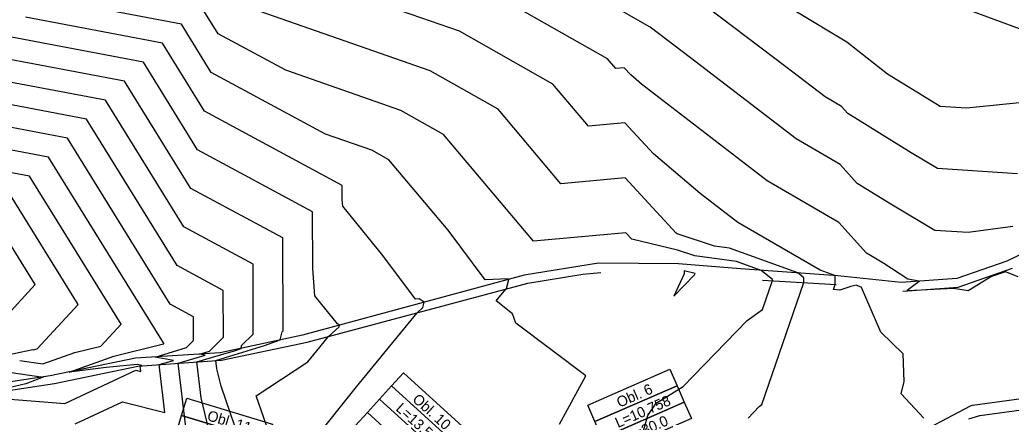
# Model space of a CAD drawing. Extents: x -549394 to -546608, y -1037055 to -1033629.
# Drawn here: x -548286 to -547954.3, y -1035512.1 to -1035379.1 of the extents above; entities that cross this region are included whole.
import ezdxf

# ---------------------------------------------------------------- set-up
doc = ezdxf.new("R2010")
doc.units = 0
for name, color, linetype in [('hlavni_vrst', 7, 'Continuous'), ('hrana_L', 7, 'Continuous'), ('norm_vrst', 7, 'Continuous'), ('x_popis_oblouky_C11', 7, 'Continuous')]:
    doc.layers.add(name, color=color, linetype=linetype)

msp = doc.modelspace()

# ---------------------------------------------------------------- linework, layer by layer
at = {"layer": 'hlavni_vrst'}
for p, q in [((-548148.73, -1035396.14), (-548210.36, -1035374.64)), ((-548009.25, -1035386.63), (-548026.31, -1035376.32)), ((-548251.01, -1035399.66), (-548323.45, -1035385.91)), ((-547995.73, -1035397.25), (-548009.25, -1035386.63)), ((-548125.97, -1035409.06), (-548148.73, -1035396.14)), ((-548228.84, -1035435.52), (-548251.01, -1035399.66)), ((-547980.98, -1035406.38), (-547995.73, -1035397.25)), ((-548104.95, -1035433.96), (-548125.97, -1035409.06)), ((-547978.09, -1035408.12), (-547980.98, -1035406.38)), ((-547969.28, -1035408.7), (-547978.09, -1035408.12)), ((-547948.12, -1035406.53), (-547969.28, -1035408.7)), ((-548282.81, -1035431.42), (-548320.94, -1035424.19)), ((-548252.16, -1035481.01), (-548282.81, -1035431.42)), ((-548083.44, -1035431.99), (-548104.95, -1035433.96)), ((-548066.37, -1035450.47), (-548083.44, -1035431.99)), ((-548198.04, -1035452.13), (-548228.84, -1035435.52)), ((-548197.94, -1035483.23), (-548198.04, -1035452.13)), ((-548066.01, -1035450.77), (-548066.37, -1035450.47)), ((-548053.6, -1035454.84), (-548066.01, -1035450.77)), ((-548048.53, -1035455.53), (-548053.6, -1035454.84)), ((-548025.63, -1035463.85), (-548048.53, -1035455.53)), ((-548023.69, -1035465.43), (-548025.63, -1035463.85)), ((-548023.71, -1035467.04), (-548023.69, -1035465.43)), ((-548037.74, -1035507.93), (-548023.71, -1035467.04)), ((-548258.92, -1035488.34), (-548252.16, -1035481.01)), ((-548198.87, -1035486.25), (-548198.29, -1035483.58)), ((-548198.29, -1035483.58), (-548197.94, -1035483.23)), ((-548267.66, -1035490.52), (-548258.92, -1035488.34)), ((-548218.62, -1035492.6), (-548204.13, -1035488.14)), ((-548204.13, -1035488.14), (-548198.87, -1035486.25)), ((-548278.38, -1035494.31), (-548267.66, -1035490.52)), ((-548286.05, -1035493.2), (-548278.38, -1035494.31)), ((-548220.44, -1035493.13), (-548218.62, -1035492.6)), ((-548220.1, -1035495.92), (-548220.44, -1035493.13)), ((-548218.72, -1035501.7), (-548220.1, -1035495.92)), ((-548212.33, -1035520.2), (-548218.72, -1035501.7)), ((-548042.35, -1035512.4), (-548038.63, -1035508.58)), ((-548038.63, -1035508.58), (-548037.74, -1035507.93))]:
    msp.add_line(p, q, dxfattribs=at)
at = {"layer": 'hrana_L'}
for p, q in [((-547937.9, -1035451.29), (-547955.7, -1035459.9)), ((-548092.43, -1035460.6), (-548117.3, -1035464.61)), ((-548065.59, -1035460.83), (-548092.43, -1035460.6)), ((-548044.85, -1035462.5), (-548065.59, -1035460.83)), ((-548012.33, -1035464.78), (-548044.85, -1035462.5)), ((-547955.7, -1035459.9), (-547972.5, -1035465.74)), ((-547972.01, -1035468.6), (-547953.79, -1035462.21)), ((-548117.3, -1035464.61), (-548191.5, -1035484.65)), ((-548115.99, -1035467.23), (-548097.61, -1035464.2)), ((-548097.61, -1035464.2), (-548091.63, -1035463.63)), ((-547991.14, -1035467), (-548012.33, -1035464.78)), ((-547972.5, -1035465.74), (-547991.14, -1035467)), ((-548189.89, -1035486.99), (-548118.94, -1035468.07)), ((-548118.94, -1035468.07), (-548115.99, -1035467.23)), ((-548037.46, -1035466.21), (-548012.89, -1035467.69)), ((-547990.56, -1035469.94), (-547972.01, -1035468.6)), ((-548191.5, -1035484.65), (-548219, -1035490.61)), ((-548218.54, -1035492.99), (-548189.89, -1035486.99)), ((-548247.31, -1035492.39), (-548275.92, -1035498.32)), ((-548219, -1035490.61), (-548247.31, -1035492.39)), ((-548274.43, -1035500.8), (-548246.59, -1035495.02)), ((-548246.59, -1035495.02), (-548218.54, -1035492.99)), ((-548275.92, -1035498.32), (-548295.3, -1035501.2)), ((-548296.13, -1035504.17), (-548274.43, -1035500.8))]:
    msp.add_line(p, q, dxfattribs=at)
at = {"layer": 'norm_vrst'}
for p, q in [((-548138.95, -1035382.85), (-548199.35, -1035361.78)), ((-547949.34, -1035382.95), (-548005.35, -1035362.14)), ((-548089.36, -1035392.15), (-548129.17, -1035369.56)), ((-548075.07, -1035381.53), (-548096.03, -1035369.52)), ((-548029.66, -1035394.85), (-548062.5, -1035369.98)), ((-548231.93, -1035380.6), (-548264.5, -1035374.42)), ((-548219.67, -1035383.79), (-548225.57, -1035374.25)), ((-548238.29, -1035386.96), (-548284.15, -1035378.25)), ((-548244.65, -1035393.31), (-548303.8, -1035382.08)), ((-548221.97, -1035396.72), (-548231.93, -1035380.6)), ((-548107.67, -1035400.6), (-548138.95, -1035382.85)), ((-548061.55, -1035391.77), (-548075.07, -1035381.53)), ((-548197.06, -1035395.99), (-548219.67, -1035383.79)), ((-548224.26, -1035409.65), (-548238.29, -1035386.96)), ((-548257.37, -1035406.01), (-548335.42, -1035391.2)), ((-548086.62, -1035395.39), (-548089.36, -1035392.15)), ((-548026.29, -1035418.94), (-548061.55, -1035391.77)), ((-548226.55, -1035422.58), (-548244.65, -1035393.31)), ((-548158.51, -1035409.43), (-548197.06, -1035395.99)), ((-548083.81, -1035395.14), (-548086.62, -1035395.39)), ((-548081.59, -1035397.55), (-548083.81, -1035395.14)), ((-548016.58, -1035404.93), (-548029.66, -1035394.85)), ((-548263.73, -1035412.37), (-548331.8, -1035399.45)), ((-548183.76, -1035417.33), (-548221.97, -1035396.72)), ((-548077.98, -1035400.6), (-548081.59, -1035397.55)), ((-548095.78, -1035414.68), (-548107.67, -1035400.6)), ((-548036, -1035432.95), (-548077.98, -1035400.6)), ((-548231.14, -1035448.45), (-548257.37, -1035406.01)), ((-548011.1, -1035408.12), (-548016.58, -1035404.93)), ((-548270.09, -1035418.72), (-548328.18, -1035407.69)), ((-548178.13, -1035434.53), (-548224.26, -1035409.65)), ((-548144.28, -1035417.51), (-548158.51, -1035409.43)), ((-548008.99, -1035410.46), (-548011.1, -1035408.12)), ((-548233.43, -1035461.38), (-548263.73, -1035412.37)), ((-547987.79, -1035423.59), (-548008.99, -1035410.46)), ((-548276.45, -1035425.07), (-548324.56, -1035415.94)), ((-548083.63, -1035413.56), (-548095.78, -1035414.68)), ((-548073.98, -1035424.01), (-548083.63, -1035413.56)), ((-548235.72, -1035474.31), (-548270.09, -1035418.72)), ((-548168.3, -1035422.73), (-548183.76, -1035417.33)), ((-548114.11, -1035453.24), (-548144.28, -1035417.51)), ((-548011.52, -1035427.52), (-548026.29, -1035418.94)), ((-548188.09, -1035443.33), (-548226.55, -1035422.58)), ((-548162.59, -1035425.97), (-548168.3, -1035422.73)), ((-548238.01, -1035487.24), (-548276.45, -1035425.07)), ((-548142.69, -1035449.53), (-548162.59, -1035425.97)), ((-548058.33, -1035437.23), (-548073.98, -1035424.01)), ((-547978.98, -1035428.86), (-547987.79, -1035423.59)), ((-548005.84, -1035433.84), (-548011.52, -1035427.52)), ((-547952.19, -1035430.64), (-547978.98, -1035428.86)), ((-548178.12, -1035439.25), (-548178.13, -1035434.53)), ((-548011.94, -1035446.93), (-548036, -1035432.95)), ((-547994.59, -1035440.8), (-548005.84, -1035433.84)), ((-548266.54, -1035474.38), (-548289.17, -1035437.78)), ((-548177.95, -1035441.52), (-548178.12, -1035439.25)), ((-548045.71, -1035446.96), (-548058.33, -1035437.23)), ((-548164.55, -1035457.95), (-548177.95, -1035441.52)), ((-547979.87, -1035449.61), (-547994.59, -1035440.8)), ((-548280.92, -1035467.75), (-548295.53, -1035444.13)), ((-548188.02, -1035462.34), (-548188.09, -1035443.33)), ((-548208, -1035460.93), (-548231.14, -1035448.45)), ((-548018.22, -1035462.93), (-548045.71, -1035446.96)), ((-548002.69, -1035457.21), (-548011.94, -1035446.93)), ((-547953.77, -1035448.32), (-547968.72, -1035450.35)), ((-548130.34, -1035466.12), (-548142.69, -1035449.53)), ((-548083.25, -1035450.41), (-548114.11, -1035453.24)), ((-548081.26, -1035452.57), (-548083.25, -1035450.41)), ((-548065.91, -1035456.19), (-548081.26, -1035452.57)), ((-547968.72, -1035450.35), (-547979.87, -1035449.61)), ((-548153.64, -1035472.6), (-548164.55, -1035457.95)), ((-548060.11, -1035458.09), (-548065.91, -1035456.19)), ((-548046.17, -1035460), (-548060.11, -1035458.09)), ((-548001.4, -1035458.01), (-548002.69, -1035457.21)), ((-547996.91, -1035460.69), (-548001.4, -1035458.01)), ((-548217.95, -1035469.73), (-548233.43, -1035461.38)), ((-548207.92, -1035484.29), (-548208, -1035460.93)), ((-548187.36, -1035471.47), (-548188.02, -1035462.34)), ((-548037.95, -1035462.98), (-548046.17, -1035460)), ((-547988.82, -1035465.93), (-547996.91, -1035460.69)), ((-548122.65, -1035465.82), (-548130.34, -1035466.12)), ((-548123.14, -1035469.03), (-548122.4, -1035465.99)), ((-548122.4, -1035465.99), (-548122.65, -1035465.82)), ((-548063.68, -1035464.11), (-548067.21, -1035471.66)), ((-548067.21, -1035471.66), (-548060.26, -1035464.43)), ((-548060, -1035464), (-548063.7, -1035463.12)), ((-548063.7, -1035463.12), (-548063.68, -1035464.11)), ((-548060.26, -1035464.43), (-548060, -1035464)), ((-548034.2, -1035466.02), (-548037.95, -1035462.98)), ((-548034.21, -1035466.41), (-548034.2, -1035466.02)), ((-548013.32, -1035464.71), (-548018.22, -1035462.93)), ((-548013.17, -1035464.83), (-548013.32, -1035464.71)), ((-548013.21, -1035467.67), (-548013.17, -1035464.83)), ((-547985.11, -1035466.59), (-547988.82, -1035465.93)), ((-547960.89, -1035465.04), (-547968.71, -1035469.77)), ((-547956.16, -1035463.44), (-547960.89, -1035465.04)), ((-547952, -1035465.1), (-547956.16, -1035463.44)), ((-548290.21, -1035477.82), (-548280.92, -1035467.75)), ((-548126.64, -1035473.22), (-548123.39, -1035469.26)), ((-548123.39, -1035469.26), (-548123.14, -1035469.03)), ((-548037.53, -1035476.08), (-548034.21, -1035466.41)), ((-548013.8, -1035469.41), (-548013.21, -1035467.67)), ((-548007.92, -1035468.32), (-548011.64, -1035469.61)), ((-548006.15, -1035467.95), (-548007.92, -1035468.32)), ((-548004.31, -1035468.7), (-548006.15, -1035467.95)), ((-548004.33, -1035468.76), (-548004.31, -1035468.7)), ((-547997.86, -1035483.64), (-548004.33, -1035468.76)), ((-547989.12, -1035469.6), (-547985.11, -1035466.59)), ((-547973.56, -1035469.05), (-547988.71, -1035469.81)), ((-547968.71, -1035469.77), (-547973.56, -1035469.05)), ((-548217.9, -1035485.35), (-548217.95, -1035469.73)), ((-548179.72, -1035480.84), (-548187.36, -1035471.47)), ((-548152.36, -1035472.55), (-548153.64, -1035472.6)), ((-548150.72, -1035473.64), (-548152.36, -1035472.55)), ((-548011.64, -1035469.61), (-548013.8, -1035469.41)), ((-547988.71, -1035469.81), (-547989.12, -1035469.6)), ((-548280.21, -1035489.2), (-548266.54, -1035474.38)), ((-548227.91, -1035478.53), (-548235.72, -1035474.31)), ((-548153.08, -1035477.17), (-548151.16, -1035475.43)), ((-548151.16, -1035475.43), (-548150.72, -1035473.64)), ((-548121.16, -1035477.49), (-548126.64, -1035473.22)), ((-548227.88, -1035486.42), (-548227.91, -1035478.53)), ((-548173.43, -1035501.96), (-548153.08, -1035477.17)), ((-548120.09, -1035480.68), (-548121.16, -1035477.49)), ((-548042.66, -1035479.8), (-548037.53, -1035476.08)), ((-548182.77, -1035485.09), (-548179.17, -1035481.83)), ((-548179.04, -1035481.28), (-548179.72, -1035480.84)), ((-548179.17, -1035481.83), (-548179.04, -1035481.28)), ((-548096.64, -1035498.3), (-548120.09, -1035480.68)), ((-548064.07, -1035501.86), (-548042.66, -1035479.8)), ((-548222.6, -1035490.02), (-548217.9, -1035485.35)), ((-548211.83, -1035488.17), (-548207.92, -1035484.29)), ((-548186.7, -1035489.89), (-548182.77, -1035485.09)), ((-547990.46, -1035490.94), (-547997.86, -1035483.64)), ((-548280.71, -1035489.32), (-548280.21, -1035489.2)), ((-548254.62, -1035491.72), (-548238.38, -1035487.67)), ((-548240.79, -1035491.98), (-548230.25, -1035488.77)), ((-548238.38, -1035487.67), (-548237.91, -1035487.52)), ((-548237.86, -1035487.32), (-548238.01, -1035487.24)), ((-548237.91, -1035487.52), (-548237.86, -1035487.48)), ((-548237.86, -1035487.48), (-548237.86, -1035487.32)), ((-548230.25, -1035488.77), (-548227.88, -1035486.42)), ((-548213.85, -1035489.75), (-548212.03, -1035489.1)), ((-548212.03, -1035489.1), (-548211.83, -1035488.17)), ((-548292.3, -1035491.67), (-548281.75, -1035489.47)), ((-548281.75, -1035489.47), (-548281.31, -1035489.54)), ((-548281.31, -1035489.54), (-548280.71, -1035489.32)), ((-548269.56, -1035497), (-548254.62, -1035491.72)), ((-548234.6, -1035493.1), (-548240.79, -1035491.98)), ((-548233.1, -1035494.04), (-548223.99, -1035491.41)), ((-548226.77, -1035493.59), (-548218.87, -1035491.3)), ((-548225.97, -1035491.05), (-548222.6, -1035490.02)), ((-548223.99, -1035491.41), (-548225.97, -1035491.05)), ((-548218.87, -1035491.3), (-548213.85, -1035489.75)), ((-548189.65, -1035493.57), (-548186.7, -1035489.89)), ((-547990.11, -1035500.23), (-547990.46, -1035490.94)), ((-548257.17, -1035495.45), (-548269.56, -1035497)), ((-548246.73, -1035494.52), (-548257.17, -1035495.45)), ((-548245.21, -1035494.8), (-548246.73, -1035494.52)), ((-548245.77, -1035494.96), (-548245.21, -1035494.8)), ((-548245.54, -1035496.81), (-548245.77, -1035494.96)), ((-548239.44, -1035494.5), (-548234.6, -1035493.1)), ((-548237.49, -1035510.59), (-548239.44, -1035494.5)), ((-548230.52, -1035515.42), (-548233.1, -1035494.04)), ((-548225.31, -1035505.67), (-548226.77, -1035493.59)), ((-548206.95, -1035504.99), (-548189.65, -1035493.57)), ((-548290.35, -1035496.92), (-548278.29, -1035498.67)), ((-548278.29, -1035498.67), (-548284.03, -1035500.98)), ((-548271.01, -1035507.52), (-548247.18, -1035496.4)), ((-548247.18, -1035496.4), (-548245.54, -1035496.81)), ((-548105.45, -1035514.49), (-548096.64, -1035498.3)), ((-548284.03, -1035500.98), (-548296, -1035503.71)), ((-548188.67, -1035521), (-548173.43, -1035501.96)), ((-548073.07, -1035507.45), (-548064.07, -1035501.86)), ((-547991.06, -1035504.34), (-547990.11, -1035500.23)), ((-548293.78, -1035505.74), (-548271.01, -1035507.52)), ((-548222.1, -1035519.12), (-548225.31, -1035505.67)), ((-548201.06, -1035522.01), (-548206.95, -1035504.99)), ((-547983.55, -1035512.45), (-547991.06, -1035504.34)), ((-547967.21, -1035508.09), (-547941.64, -1035504.6)), ((-548267.52, -1035514.38), (-548251.74, -1035507.02)), ((-548251.74, -1035507.02), (-548237.49, -1035510.59)), ((-548075.93, -1035511.56), (-548073.07, -1035507.45)), ((-548000.93, -1035525.72), (-547967.91, -1035508.32)), ((-547967.91, -1035508.32), (-547967.21, -1035508.09)), ((-547964.78, -1035511.52), (-547941.7, -1035508.37)), ((-548078.76, -1035521.75), (-548075.93, -1035511.56)), ((-547968.42, -1035512.71), (-547964.78, -1035511.52))]:
    msp.add_line(p, q, dxfattribs=at)
at = {"layer": 'x_popis_oblouky_C11'}
for points in [[(-548157.63, -1035497.23), (-548135.44, -1035517.43), (-548139.48, -1035521.87), (-548161.67, -1035501.67)], [(-548096, -1035508.12), (-548068.51, -1035496.09), (-548066.11, -1035501.59), (-548093.59, -1035513.62)], [(-548161.67, -1035501.67), (-548139.48, -1035521.87), (-548143.52, -1035526.3), (-548165.71, -1035506.11)], [(-548093.59, -1035513.62), (-548066.11, -1035501.59), (-548063.7, -1035507.09), (-548091.18, -1035519.11)], [(-548230.19, -1035505.8), (-548201.48, -1035514.49), (-548203.21, -1035520.24), (-548231.93, -1035511.54)], [(-548165.71, -1035506.11), (-548143.52, -1035526.3), (-548147.56, -1035530.74), (-548169.75, -1035510.55)], [(-548091.18, -1035519.11), (-548063.7, -1035507.09), (-548061.3, -1035512.58), (-548088.78, -1035524.61)], [(-548231.93, -1035511.54), (-548203.21, -1035520.24), (-548204.95, -1035525.98), (-548233.67, -1035517.29)], [(-548169.75, -1035510.55), (-548147.56, -1035530.74), (-548151.6, -1035535.18), (-548173.79, -1035514.98)]]:
    msp.add_lwpolyline(points, close=True, dxfattribs=at)

# ---------------------------------------------------------------- texts
for s, rotation, p in [('Obl. 6', 23.6574, (-548085.35, -1035508.98)), ('Obl. 10', 317.7116, (-548154.93, -1035506.52)), ('L=10.758', 23.6574, (-548085.88, -1035515.76)), ('L=13.594', 317.7116, (-548160.48, -1035509.59)), ('Obl. 11', 343.1781, (-548223.61, -1035513.07)), ('r=30.0', 23.6574, (-548080.98, -1035519.98))]:
    msp.add_text(s, height=3.5, rotation=rotation, dxfattribs=at).set_placement(p)

doc.saveas('drawing.dxf')
